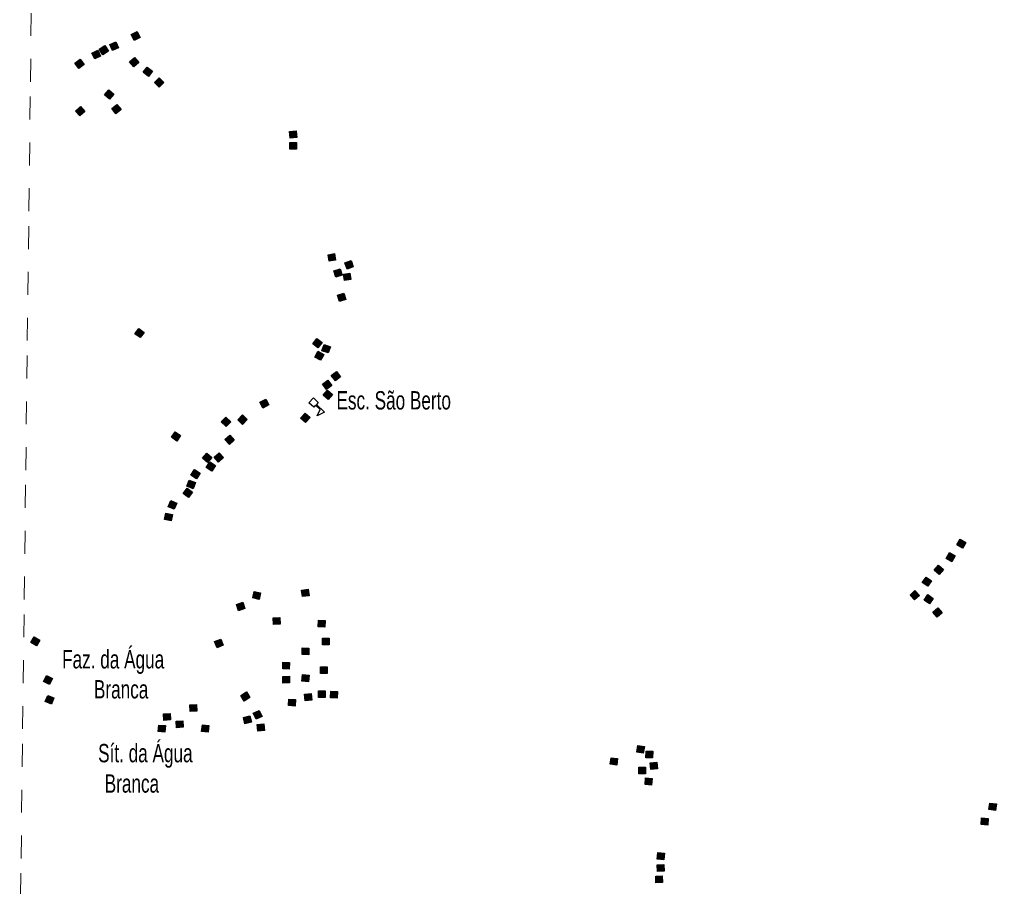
# Model space of a CAD drawing. Extents: x 679 to 705, y 7427.4 to 7455.4.
# Drawn here: x 679.18 to 683.442, y 7439.999 to 7443.783 of the extents above; entities that cross this region are included whole.
import ezdxf

# ---------------------------------------------------------------- set-up
doc = ezdxf.new("R2010")
doc.units = 0
doc.header["$LTSCALE"] = 0.032
doc.header["$PDMODE"] = 32
doc.header["$PDSIZE"] = 0.016
doc.linetypes.add('SHORT_DASHED', pattern=[2.7, 1.5, -1.2])
for name, color, linetype, lineweight in [('2', 7, 'Continuous', 25), ('4', 7, 'Continuous', 25), ('58', 7, 'SHORT_DASHED', 13)]:
    doc.layers.add(name, color=color, linetype=linetype, lineweight=lineweight)
doc.layers.add('61', color=7, linetype='Continuous')

msp = doc.modelspace()

# ---------------------------------------------------------------- hatches: boundary and pattern name
at = {"layer": '2'}
for points in [[(679.6934, 7443.731), (679.7064, 7443.705), (679.6805, 7443.6921), (679.6675, 7443.718)], [(679.5998, 7443.6862), (679.6121, 7443.6599), (679.5859, 7443.6476), (679.5735, 7443.6738)], [(679.5214, 7443.6496), (679.5341, 7443.6235), (679.5081, 7443.6108), (679.4953, 7443.6368)], [(679.5528, 7443.6693), (679.5683, 7443.6448), (679.5438, 7443.6292), (679.5283, 7443.6537)], [(679.4447, 7443.6104), (679.4618, 7443.587), (679.4384, 7443.5699), (679.4213, 7443.5933)], [(679.6825, 7443.617), (679.7013, 7443.5949), (679.6792, 7443.5761), (679.6604, 7443.5982)], [(679.7376, 7443.5754), (679.7604, 7443.5574), (679.7425, 7443.5346), (679.7197, 7443.5526)], [(679.7893, 7443.5293), (679.8098, 7443.5088), (679.7893, 7443.4883), (679.7688, 7443.5088)], [(679.5695, 7443.4765), (679.5914, 7443.4575), (679.5724, 7443.4356), (679.5505, 7443.4546)], [(679.4458, 7443.4032), (679.4654, 7443.3818), (679.4439, 7443.3622), (679.4244, 7443.3837)], [(679.6047, 7443.4127), (679.6231, 7443.3903), (679.6006, 7443.3719), (679.5823, 7443.3944)], [(680.3866, 7443.2966), (680.3895, 7443.2677), (680.3606, 7443.2648), (680.3577, 7443.2937)], [(680.388, 7443.2459), (680.388, 7443.2169), (680.359, 7443.2169), (680.359, 7443.2459)], [(680.5547, 7442.7612), (680.5592, 7442.7325), (680.5306, 7442.728), (680.5261, 7442.7567)], [(680.6265, 7442.7311), (680.6363, 7442.7037), (680.609, 7442.694), (680.5992, 7442.7213)], [(680.5511, 7442.6863), (680.5787, 7442.6952), (680.5876, 7442.6676), (680.56, 7442.6587)], [(680.6216, 7442.6767), (680.6263, 7442.6481), (680.5977, 7442.6434), (680.593, 7442.672)], [(680.5767, 7442.5517), (680.568, 7442.5794), (680.5956, 7442.5881), (680.6044, 7442.5605)], [(679.7003, 7442.4351), (679.7234, 7442.4177), (679.706, 7442.3945), (679.6828, 7442.4119)], [(680.477, 7442.3904), (680.5, 7442.3727), (680.4823, 7442.3498), (680.4594, 7442.3674)], [(680.5097, 7442.3648), (680.5369, 7442.3548), (680.5269, 7442.3276), (680.4997, 7442.3376)], [(680.4821, 7442.3355), (680.5075, 7442.3216), (680.4936, 7442.2962), (680.4682, 7442.3101)], [(680.5632, 7442.2469), (680.5811, 7442.2241), (680.5582, 7442.2062), (680.5404, 7442.2291)], [(680.5256, 7442.2086), (680.5427, 7442.1851), (680.5192, 7442.168), (680.5022, 7442.1915)], [(680.5243, 7442.1656), (680.5463, 7442.1467), (680.5274, 7442.1247), (680.5054, 7442.1436)], [(680.2542, 7442.1266), (680.2676, 7442.1008), (680.2418, 7442.0875), (680.2285, 7442.1132)], [(680.4259, 7442.0651), (680.4475, 7442.0457), (680.4281, 7442.0242), (680.4065, 7442.0436)], [(680.0804, 7442.0476), (680.1014, 7442.0276), (680.0814, 7442.0066), (680.0604, 7442.0266)], [(680.1524, 7442.0572), (680.1732, 7442.037), (680.153, 7442.0162), (680.1322, 7442.0364)], [(679.859, 7441.9834), (679.8828, 7441.9669), (679.8663, 7441.9431), (679.8425, 7441.9596)], [(680.0979, 7441.9694), (680.1172, 7441.9478), (680.0956, 7441.9285), (680.0763, 7441.9501)], [(679.997, 7441.8908), (680.0192, 7441.8721), (680.0005, 7441.85), (679.9783, 7441.8687)], [(680.0509, 7441.8925), (680.0701, 7441.8708), (680.0483, 7441.8516), (680.0292, 7441.8733)], [(680.0101, 7441.852), (680.0348, 7441.8369), (680.0197, 7441.8122), (679.995, 7441.8273)], [(679.9432, 7441.8185), (679.9679, 7441.8033), (679.9527, 7441.7786), (679.928, 7441.7938)], [(679.9208, 7441.7728), (679.9478, 7441.7621), (679.9371, 7441.7351), (679.9102, 7441.7458)], [(679.9119, 7441.7376), (679.9347, 7441.7196), (679.9167, 7441.6969), (679.8939, 7441.7148)], [(679.8399, 7441.6836), (679.8666, 7441.6724), (679.8554, 7441.6456), (679.8287, 7441.6568)], [(679.8189, 7441.629), (679.8474, 7441.6234), (679.8418, 7441.595), (679.8133, 7441.6005)], [(683.2839, 7441.5154), (683.3087, 7441.5004), (683.2937, 7441.4755), (683.2689, 7441.4905)], [(683.2373, 7441.4562), (683.2624, 7441.4417), (683.2478, 7441.4166), (683.2227, 7441.4312)], [(683.1898, 7441.401), (683.2118, 7441.3821), (683.1929, 7441.3601), (683.1709, 7441.3791)], [(683.1351, 7441.3497), (683.159, 7441.3333), (683.1426, 7441.3094), (683.1187, 7441.3257)], [(680.4394, 7441.2968), (680.4432, 7441.2681), (680.4145, 7441.2642), (680.4106, 7441.2929)], [(680.2319, 7441.2808), (680.2258, 7441.2524), (680.1974, 7441.2586), (680.2036, 7441.2869)], [(683.0868, 7441.291), (683.1065, 7441.2697), (683.0852, 7441.25), (683.0655, 7441.2713)], [(683.1433, 7441.2731), (683.167, 7441.2565), (683.1504, 7441.2328), (683.1266, 7441.2494)], [(680.1539, 7441.2397), (680.1633, 7441.2123), (680.1359, 7441.2029), (680.1265, 7441.2303)], [(683.1863, 7441.216), (683.2052, 7441.1941), (683.1833, 7441.1751), (683.1643, 7441.1971)], [(680.3165, 7441.1727), (680.3175, 7441.1437), (680.2885, 7441.1428), (680.2875, 7441.1718)], [(680.5137, 7441.1605), (680.5124, 7441.1316), (680.4835, 7441.1328), (680.4847, 7441.1618)], [(679.2434, 7441.0889), (679.2686, 7441.0745), (679.2541, 7441.0493), (679.229, 7441.0638)], [(680.5317, 7441.0826), (680.5317, 7441.0536), (680.5027, 7441.0536), (680.5027, 7441.0826)], [(680.0581, 7441.0786), (680.0689, 7441.0517), (680.042, 7441.041), (680.0312, 7441.0679)], [(680.4429, 7441.0391), (680.4419, 7441.0101), (680.4129, 7441.0111), (680.4139, 7441.0401)], [(680.3585, 7440.9767), (680.3573, 7440.9478), (680.3283, 7440.949), (680.3295, 7440.9779)], [(680.5221, 7440.9582), (680.5221, 7440.9292), (680.4931, 7440.9292), (680.4931, 7440.9582)], [(679.298, 7440.9194), (679.3241, 7440.9067), (679.3113, 7440.8806), (679.2853, 7440.8934)], [(680.3575, 7440.9171), (680.3583, 7440.8881), (680.3294, 7440.8872), (680.3285, 7440.9162)], [(680.4436, 7440.9218), (680.441, 7440.8929), (680.4121, 7440.8955), (680.4147, 7440.9244)], [(679.303, 7440.8327), (679.33, 7440.822), (679.3192, 7440.795), (679.2923, 7440.8058)], [(680.17, 7440.8483), (680.1849, 7440.8234), (680.16, 7440.8085), (680.1451, 7440.8333)], [(680.4519, 7440.8415), (680.4552, 7440.8127), (680.4264, 7440.8094), (680.4231, 7440.8383)], [(680.5142, 7440.8529), (680.5142, 7440.8239), (680.4852, 7440.8239), (680.4852, 7440.8529)], [(680.5673, 7440.8507), (680.5662, 7440.8217), (680.5372, 7440.8229), (680.5383, 7440.8519)], [(679.9521, 7440.7927), (679.9532, 7440.7638), (679.9242, 7440.7627), (679.9231, 7440.7916)], [(680.3843, 7440.8152), (680.3823, 7440.7863), (680.3534, 7440.7883), (680.3554, 7440.8172)], [(679.8369, 7440.7548), (679.8387, 7440.7258), (679.8098, 7440.724), (679.808, 7440.753)], [(680.1848, 7440.744), (680.1919, 7440.7159), (680.1637, 7440.7089), (680.1567, 7440.737)], [(680.2263, 7440.7679), (680.2383, 7440.7415), (680.2119, 7440.7295), (680.1999, 7440.7559)], [(679.8164, 7440.7019), (679.8144, 7440.673), (679.7855, 7440.675), (679.7875, 7440.7039)], [(679.8929, 7440.7228), (679.8944, 7440.6938), (679.8655, 7440.6922), (679.8639, 7440.7212)], [(680.0067, 7440.7014), (680.0035, 7440.6725), (679.9747, 7440.6756), (679.9778, 7440.7045)], [(680.2462, 7440.7089), (680.249, 7440.68), (680.2201, 7440.6773), (680.2173, 7440.7061)], [(681.9062, 7440.6097), (681.9018, 7440.5811), (681.8731, 7440.5855), (681.8775, 7440.6141)], [(681.9429, 7440.5892), (681.942, 7440.5602), (681.913, 7440.5611), (681.9139, 7440.5901)], [(681.7896, 7440.5573), (681.7857, 7440.5286), (681.7569, 7440.5325), (681.7608, 7440.5613)], [(681.9601, 7440.5415), (681.9631, 7440.5127), (681.9343, 7440.5096), (681.9312, 7440.5384)], [(681.9106, 7440.5194), (681.9106, 7440.4904), (681.8816, 7440.4904), (681.8816, 7440.5194)], [(681.9403, 7440.4705), (681.9381, 7440.4416), (681.9092, 7440.4438), (681.9114, 7440.4727)], [(683.4425, 7440.3596), (683.4387, 7440.3308), (683.4099, 7440.3346), (683.4137, 7440.3634)], [(683.4067, 7440.2959), (683.4043, 7440.267), (683.3754, 7440.2693), (683.3778, 7440.2982)], [(681.9944, 7440.144), (681.9914, 7440.1151), (681.9626, 7440.1182), (681.9656, 7440.147)], [(681.9906, 7440.0952), (681.9924, 7440.0663), (681.9634, 7440.0645), (681.9616, 7440.0934)], [(681.9847, 7440.0454), (681.9855, 7440.0164), (681.9566, 7440.0155), (681.9557, 7440.0445)]]:
    msp.add_hatch(color=256, dxfattribs=at).paths.add_polyline_path(points)

# ---------------------------------------------------------------- linework, layer by layer
for points in [[(679.6934, 7443.731), (679.7064, 7443.705), (679.6805, 7443.6921), (679.6675, 7443.718)], [(679.5998, 7443.6862), (679.6121, 7443.6599), (679.5859, 7443.6476), (679.5735, 7443.6738)], [(679.5214, 7443.6496), (679.5341, 7443.6235), (679.5081, 7443.6108), (679.4953, 7443.6368)], [(679.5528, 7443.6693), (679.5683, 7443.6448), (679.5438, 7443.6292), (679.5283, 7443.6537)], [(679.4447, 7443.6104), (679.4618, 7443.587), (679.4384, 7443.5699), (679.4213, 7443.5933)], [(679.6825, 7443.617), (679.7013, 7443.5949), (679.6792, 7443.5761), (679.6604, 7443.5982)], [(679.7376, 7443.5754), (679.7604, 7443.5574), (679.7425, 7443.5346), (679.7197, 7443.5526)], [(679.7893, 7443.5293), (679.8098, 7443.5088), (679.7893, 7443.4883), (679.7688, 7443.5088)], [(679.5695, 7443.4765), (679.5914, 7443.4575), (679.5724, 7443.4356), (679.5505, 7443.4546)], [(679.4458, 7443.4032), (679.4654, 7443.3818), (679.4439, 7443.3622), (679.4244, 7443.3837)], [(679.6047, 7443.4127), (679.6231, 7443.3903), (679.6006, 7443.3719), (679.5823, 7443.3944)], [(680.3866, 7443.2966), (680.3895, 7443.2677), (680.3606, 7443.2648), (680.3577, 7443.2937)], [(680.388, 7443.2459), (680.388, 7443.2169), (680.359, 7443.2169), (680.359, 7443.2459)], [(680.5547, 7442.7612), (680.5592, 7442.7325), (680.5306, 7442.728), (680.5261, 7442.7567)], [(680.6265, 7442.7311), (680.6363, 7442.7037), (680.609, 7442.694), (680.5992, 7442.7213)], [(680.5511, 7442.6863), (680.5787, 7442.6952), (680.5876, 7442.6676), (680.56, 7442.6587)], [(680.6216, 7442.6767), (680.6263, 7442.6481), (680.5977, 7442.6434), (680.593, 7442.672)], [(680.5767, 7442.5517), (680.568, 7442.5794), (680.5956, 7442.5881), (680.6044, 7442.5605)], [(679.7003, 7442.4351), (679.7234, 7442.4177), (679.706, 7442.3945), (679.6828, 7442.4119)], [(680.477, 7442.3904), (680.5, 7442.3727), (680.4823, 7442.3498), (680.4594, 7442.3674)], [(680.5097, 7442.3648), (680.5369, 7442.3548), (680.5269, 7442.3276), (680.4997, 7442.3376)], [(680.4821, 7442.3355), (680.5075, 7442.3216), (680.4936, 7442.2962), (680.4682, 7442.3101)], [(680.5632, 7442.2469), (680.5811, 7442.2241), (680.5582, 7442.2062), (680.5404, 7442.2291)], [(680.5256, 7442.2086), (680.5427, 7442.1851), (680.5192, 7442.168), (680.5022, 7442.1915)], [(680.5243, 7442.1656), (680.5463, 7442.1467), (680.5274, 7442.1247), (680.5054, 7442.1436)], [(680.2542, 7442.1266), (680.2676, 7442.1008), (680.2418, 7442.0875), (680.2285, 7442.1132)], [(680.4259, 7442.0651), (680.4475, 7442.0457), (680.4281, 7442.0242), (680.4065, 7442.0436)], [(680.0804, 7442.0476), (680.1014, 7442.0276), (680.0814, 7442.0066), (680.0604, 7442.0266)], [(680.1524, 7442.0572), (680.1732, 7442.037), (680.153, 7442.0162), (680.1322, 7442.0364)], [(679.859, 7441.9834), (679.8828, 7441.9669), (679.8663, 7441.9431), (679.8425, 7441.9596)], [(680.0979, 7441.9694), (680.1172, 7441.9478), (680.0956, 7441.9285), (680.0763, 7441.9501)], [(679.997, 7441.8908), (680.0192, 7441.8721), (680.0005, 7441.85), (679.9783, 7441.8687)], [(680.0509, 7441.8925), (680.0701, 7441.8708), (680.0483, 7441.8516), (680.0292, 7441.8733)], [(680.0101, 7441.852), (680.0348, 7441.8369), (680.0197, 7441.8122), (679.995, 7441.8273)], [(679.9432, 7441.8185), (679.9679, 7441.8033), (679.9527, 7441.7786), (679.928, 7441.7938)], [(679.9208, 7441.7728), (679.9478, 7441.7621), (679.9371, 7441.7351), (679.9102, 7441.7458)], [(679.9119, 7441.7376), (679.9347, 7441.7196), (679.9167, 7441.6969), (679.8939, 7441.7148)], [(679.8399, 7441.6836), (679.8666, 7441.6724), (679.8554, 7441.6456), (679.8287, 7441.6568)], [(679.8189, 7441.629), (679.8474, 7441.6234), (679.8418, 7441.595), (679.8133, 7441.6005)], [(683.2839, 7441.5154), (683.3087, 7441.5004), (683.2937, 7441.4755), (683.2689, 7441.4905)], [(683.2373, 7441.4562), (683.2624, 7441.4417), (683.2478, 7441.4166), (683.2227, 7441.4312)], [(683.1898, 7441.401), (683.2118, 7441.3821), (683.1929, 7441.3601), (683.1709, 7441.3791)], [(683.1351, 7441.3497), (683.159, 7441.3333), (683.1426, 7441.3094), (683.1187, 7441.3257)], [(680.4394, 7441.2968), (680.4432, 7441.2681), (680.4145, 7441.2642), (680.4106, 7441.2929)], [(680.2319, 7441.2808), (680.2258, 7441.2524), (680.1974, 7441.2586), (680.2036, 7441.2869)], [(683.0868, 7441.291), (683.1065, 7441.2697), (683.0852, 7441.25), (683.0655, 7441.2713)], [(683.1433, 7441.2731), (683.167, 7441.2565), (683.1504, 7441.2328), (683.1266, 7441.2494)], [(680.1539, 7441.2397), (680.1633, 7441.2123), (680.1359, 7441.2029), (680.1265, 7441.2303)], [(683.1863, 7441.216), (683.2052, 7441.1941), (683.1833, 7441.1751), (683.1643, 7441.1971)], [(680.3165, 7441.1727), (680.3175, 7441.1437), (680.2885, 7441.1428), (680.2875, 7441.1718)], [(680.5137, 7441.1605), (680.5124, 7441.1316), (680.4835, 7441.1328), (680.4847, 7441.1618)], [(679.2434, 7441.0889), (679.2686, 7441.0745), (679.2541, 7441.0493), (679.229, 7441.0638)], [(680.5317, 7441.0826), (680.5317, 7441.0536), (680.5027, 7441.0536), (680.5027, 7441.0826)], [(680.0581, 7441.0786), (680.0689, 7441.0517), (680.042, 7441.041), (680.0312, 7441.0679)], [(680.4429, 7441.0391), (680.4419, 7441.0101), (680.4129, 7441.0111), (680.4139, 7441.0401)], [(680.3585, 7440.9767), (680.3573, 7440.9478), (680.3283, 7440.949), (680.3295, 7440.9779)], [(680.5221, 7440.9582), (680.5221, 7440.9292), (680.4931, 7440.9292), (680.4931, 7440.9582)], [(679.298, 7440.9194), (679.3241, 7440.9067), (679.3113, 7440.8806), (679.2853, 7440.8934)], [(680.3575, 7440.9171), (680.3583, 7440.8881), (680.3294, 7440.8872), (680.3285, 7440.9162)], [(680.4436, 7440.9218), (680.441, 7440.8929), (680.4121, 7440.8955), (680.4147, 7440.9244)], [(679.303, 7440.8327), (679.33, 7440.822), (679.3192, 7440.795), (679.2923, 7440.8058)], [(680.17, 7440.8483), (680.1849, 7440.8234), (680.16, 7440.8085), (680.1451, 7440.8333)], [(680.4519, 7440.8415), (680.4552, 7440.8127), (680.4264, 7440.8094), (680.4231, 7440.8383)], [(680.5142, 7440.8529), (680.5142, 7440.8239), (680.4852, 7440.8239), (680.4852, 7440.8529)], [(680.5673, 7440.8507), (680.5662, 7440.8217), (680.5372, 7440.8229), (680.5383, 7440.8519)], [(679.9521, 7440.7927), (679.9532, 7440.7638), (679.9242, 7440.7627), (679.9231, 7440.7916)], [(680.3843, 7440.8152), (680.3823, 7440.7863), (680.3534, 7440.7883), (680.3554, 7440.8172)], [(679.8369, 7440.7548), (679.8387, 7440.7258), (679.8098, 7440.724), (679.808, 7440.753)], [(680.1848, 7440.744), (680.1919, 7440.7159), (680.1637, 7440.7089), (680.1567, 7440.737)], [(680.2263, 7440.7679), (680.2383, 7440.7415), (680.2119, 7440.7295), (680.1999, 7440.7559)], [(679.8164, 7440.7019), (679.8144, 7440.673), (679.7855, 7440.675), (679.7875, 7440.7039)], [(679.8929, 7440.7228), (679.8944, 7440.6938), (679.8655, 7440.6922), (679.8639, 7440.7212)], [(680.0067, 7440.7014), (680.0035, 7440.6725), (679.9747, 7440.6756), (679.9778, 7440.7045)], [(680.2462, 7440.7089), (680.249, 7440.68), (680.2201, 7440.6773), (680.2173, 7440.7061)], [(681.9062, 7440.6097), (681.9018, 7440.5811), (681.8731, 7440.5855), (681.8775, 7440.6141)], [(681.9429, 7440.5892), (681.942, 7440.5602), (681.913, 7440.5611), (681.9139, 7440.5901)], [(681.7896, 7440.5573), (681.7857, 7440.5286), (681.7569, 7440.5325), (681.7608, 7440.5613)], [(681.9601, 7440.5415), (681.9631, 7440.5127), (681.9343, 7440.5096), (681.9312, 7440.5384)], [(681.9106, 7440.5194), (681.9106, 7440.4904), (681.8816, 7440.4904), (681.8816, 7440.5194)], [(681.9403, 7440.4705), (681.9381, 7440.4416), (681.9092, 7440.4438), (681.9114, 7440.4727)], [(683.4425, 7440.3596), (683.4387, 7440.3308), (683.4099, 7440.3346), (683.4137, 7440.3634)], [(683.4067, 7440.2959), (683.4043, 7440.267), (683.3754, 7440.2693), (683.3778, 7440.2982)], [(681.9944, 7440.144), (681.9914, 7440.1151), (681.9626, 7440.1182), (681.9656, 7440.147)], [(681.9906, 7440.0952), (681.9924, 7440.0663), (681.9634, 7440.0645), (681.9616, 7440.0934)], [(681.9847, 7440.0454), (681.9855, 7440.0164), (681.9566, 7440.0155), (681.9557, 7440.0445)]]:
    msp.add_lwpolyline(points, close=True, dxfattribs=at)
msp.add_point((680.1751, 7440.7289), dxfattribs=at)
at = {"layer": '4'}
for points in [[(680.4722, 7442.0993), (680.4639, 7442.0905), (680.4428, 7442.1105), (680.4628, 7442.1315), (680.4838, 7442.1116), (680.4756, 7442.1029)], [(680.4756, 7442.1029), (680.5107, 7442.0696), (680.479, 7442.053), (680.4912, 7442.0814), (680.4722, 7442.0993)]]:
    msp.add_lwpolyline(points, dxfattribs=at)
at = {"layer": '58'}
msp.add_lwpolyline([(679.1802, 7439.5566), (679.1869, 7440.1216), (679.1937, 7440.6866), (679.2005, 7441.2516), (679.2073, 7441.8166), (679.2141, 7442.3815), (679.2208, 7442.9465), (679.2276, 7443.5115), (679.2344, 7444.0765), (679.2412, 7444.6415), (679.2479, 7445.2065), (679.2547, 7445.7715), (679.2615, 7446.3365), (679.2682, 7446.9015), (679.275, 7447.4665), (679.2818, 7448.0315)], dxfattribs=at)

# ---------------------------------------------------------------- texts
at = {"layer": '61', "width": 0.7}
for s, p in [('Esc. São Berto', (680.563, 7442.081)), ('Faz. da Água ', (679.3659, 7440.9507)), ('Branca', (679.5048, 7440.8198)), ('Sít. da Água ', (679.5231, 7440.5411)), ('Branca', (679.5518, 7440.4085))]:
    msp.add_text(s, height=0.08, dxfattribs=at).set_placement(p)

doc.saveas('drawing.dxf')
